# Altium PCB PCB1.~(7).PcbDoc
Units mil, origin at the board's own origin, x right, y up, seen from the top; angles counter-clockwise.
Board outline 2228.35 x 2228.35 mil, 2 copper layers (Top Layer, Bottom Layer); 14 components, 9 nets, 44 pads, 0 vias.
Unrouted connection lines stored in the file: 2.
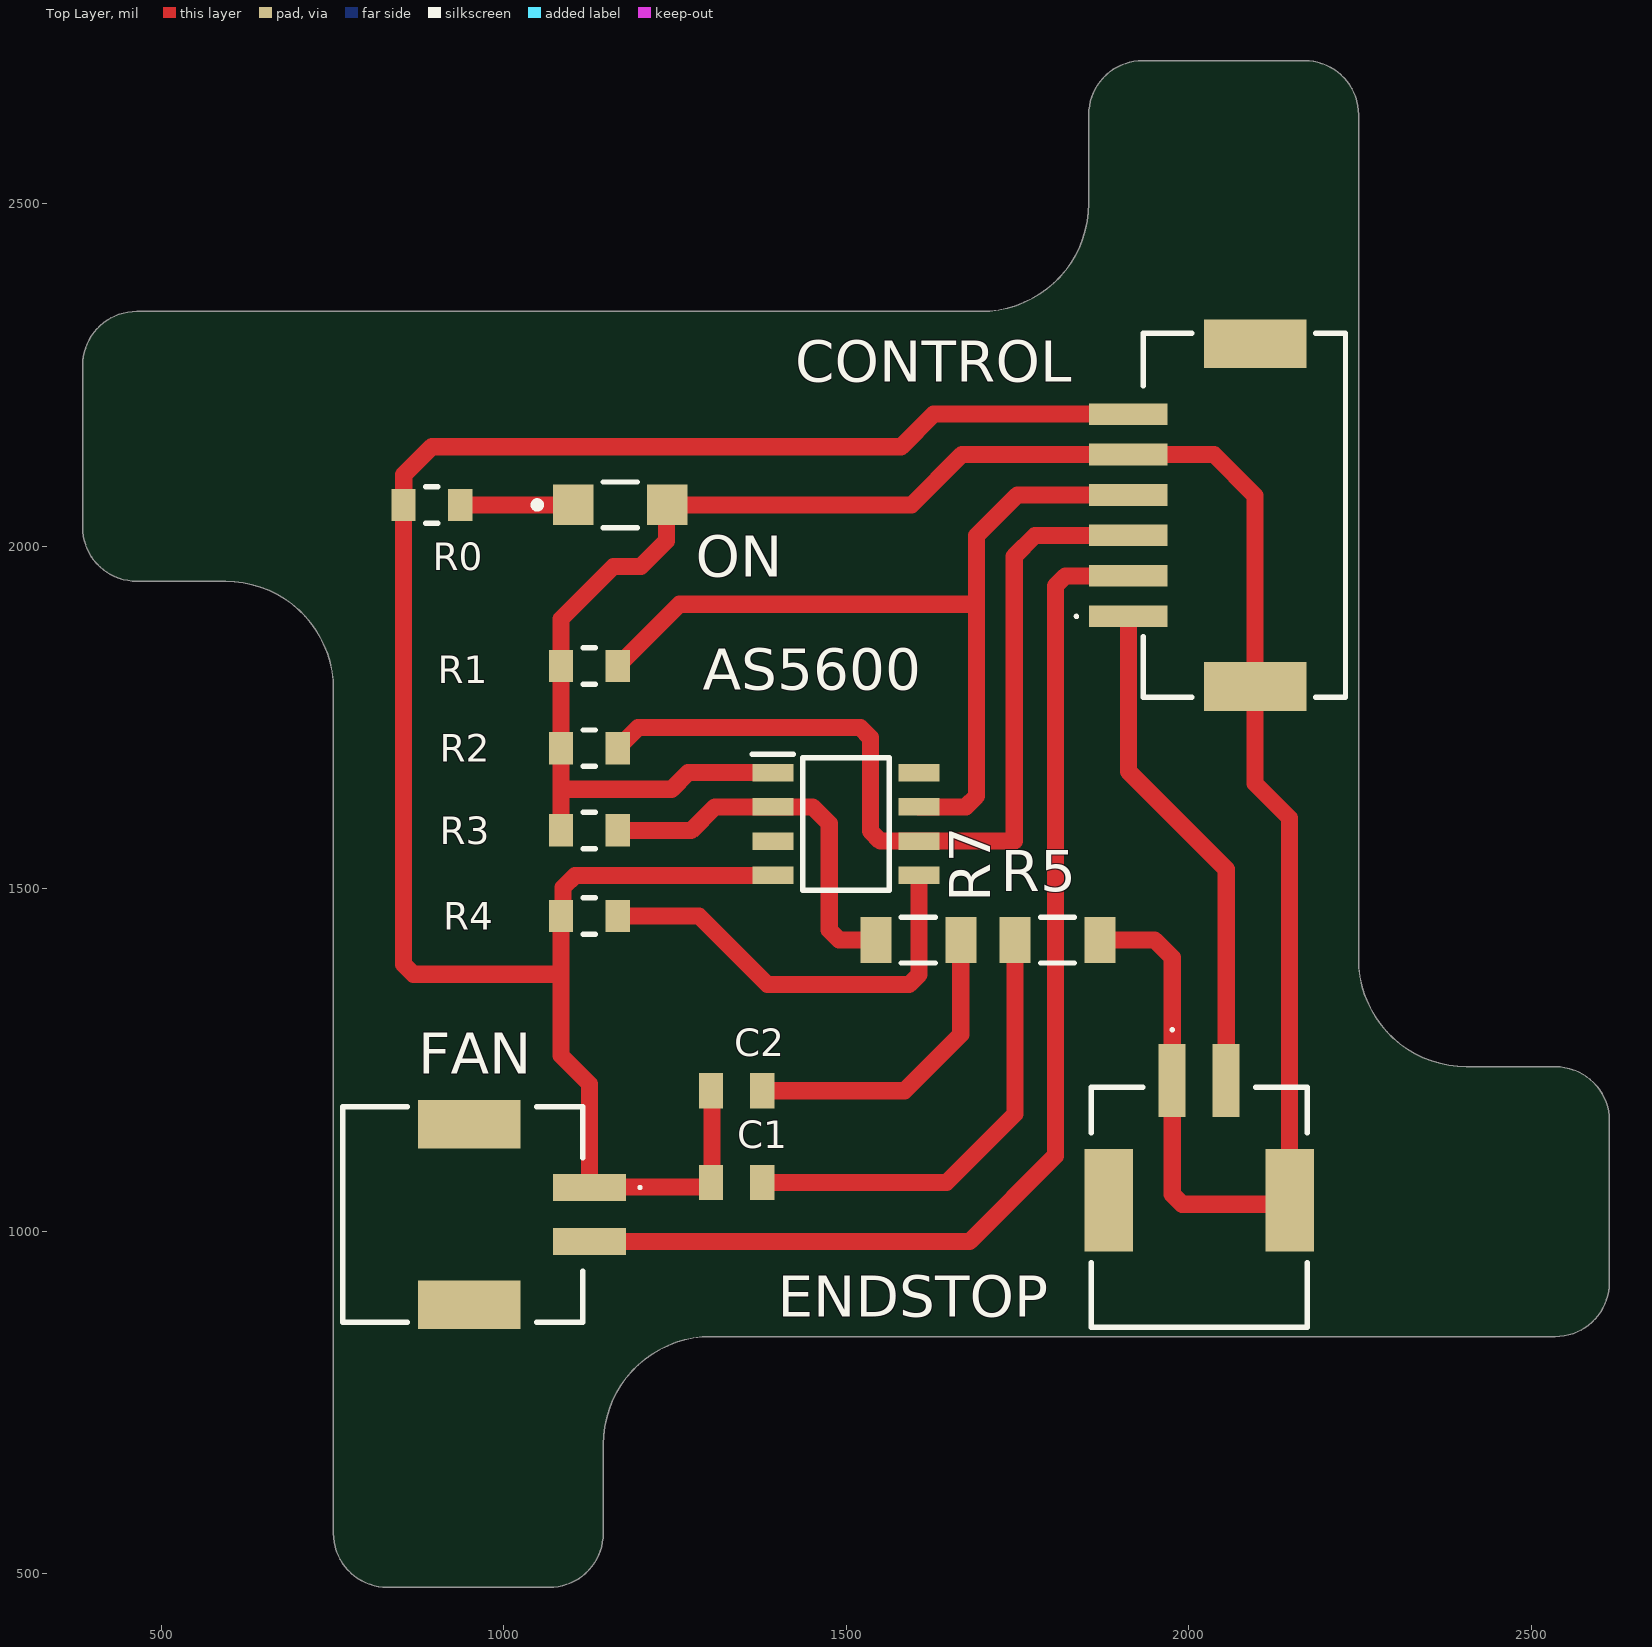
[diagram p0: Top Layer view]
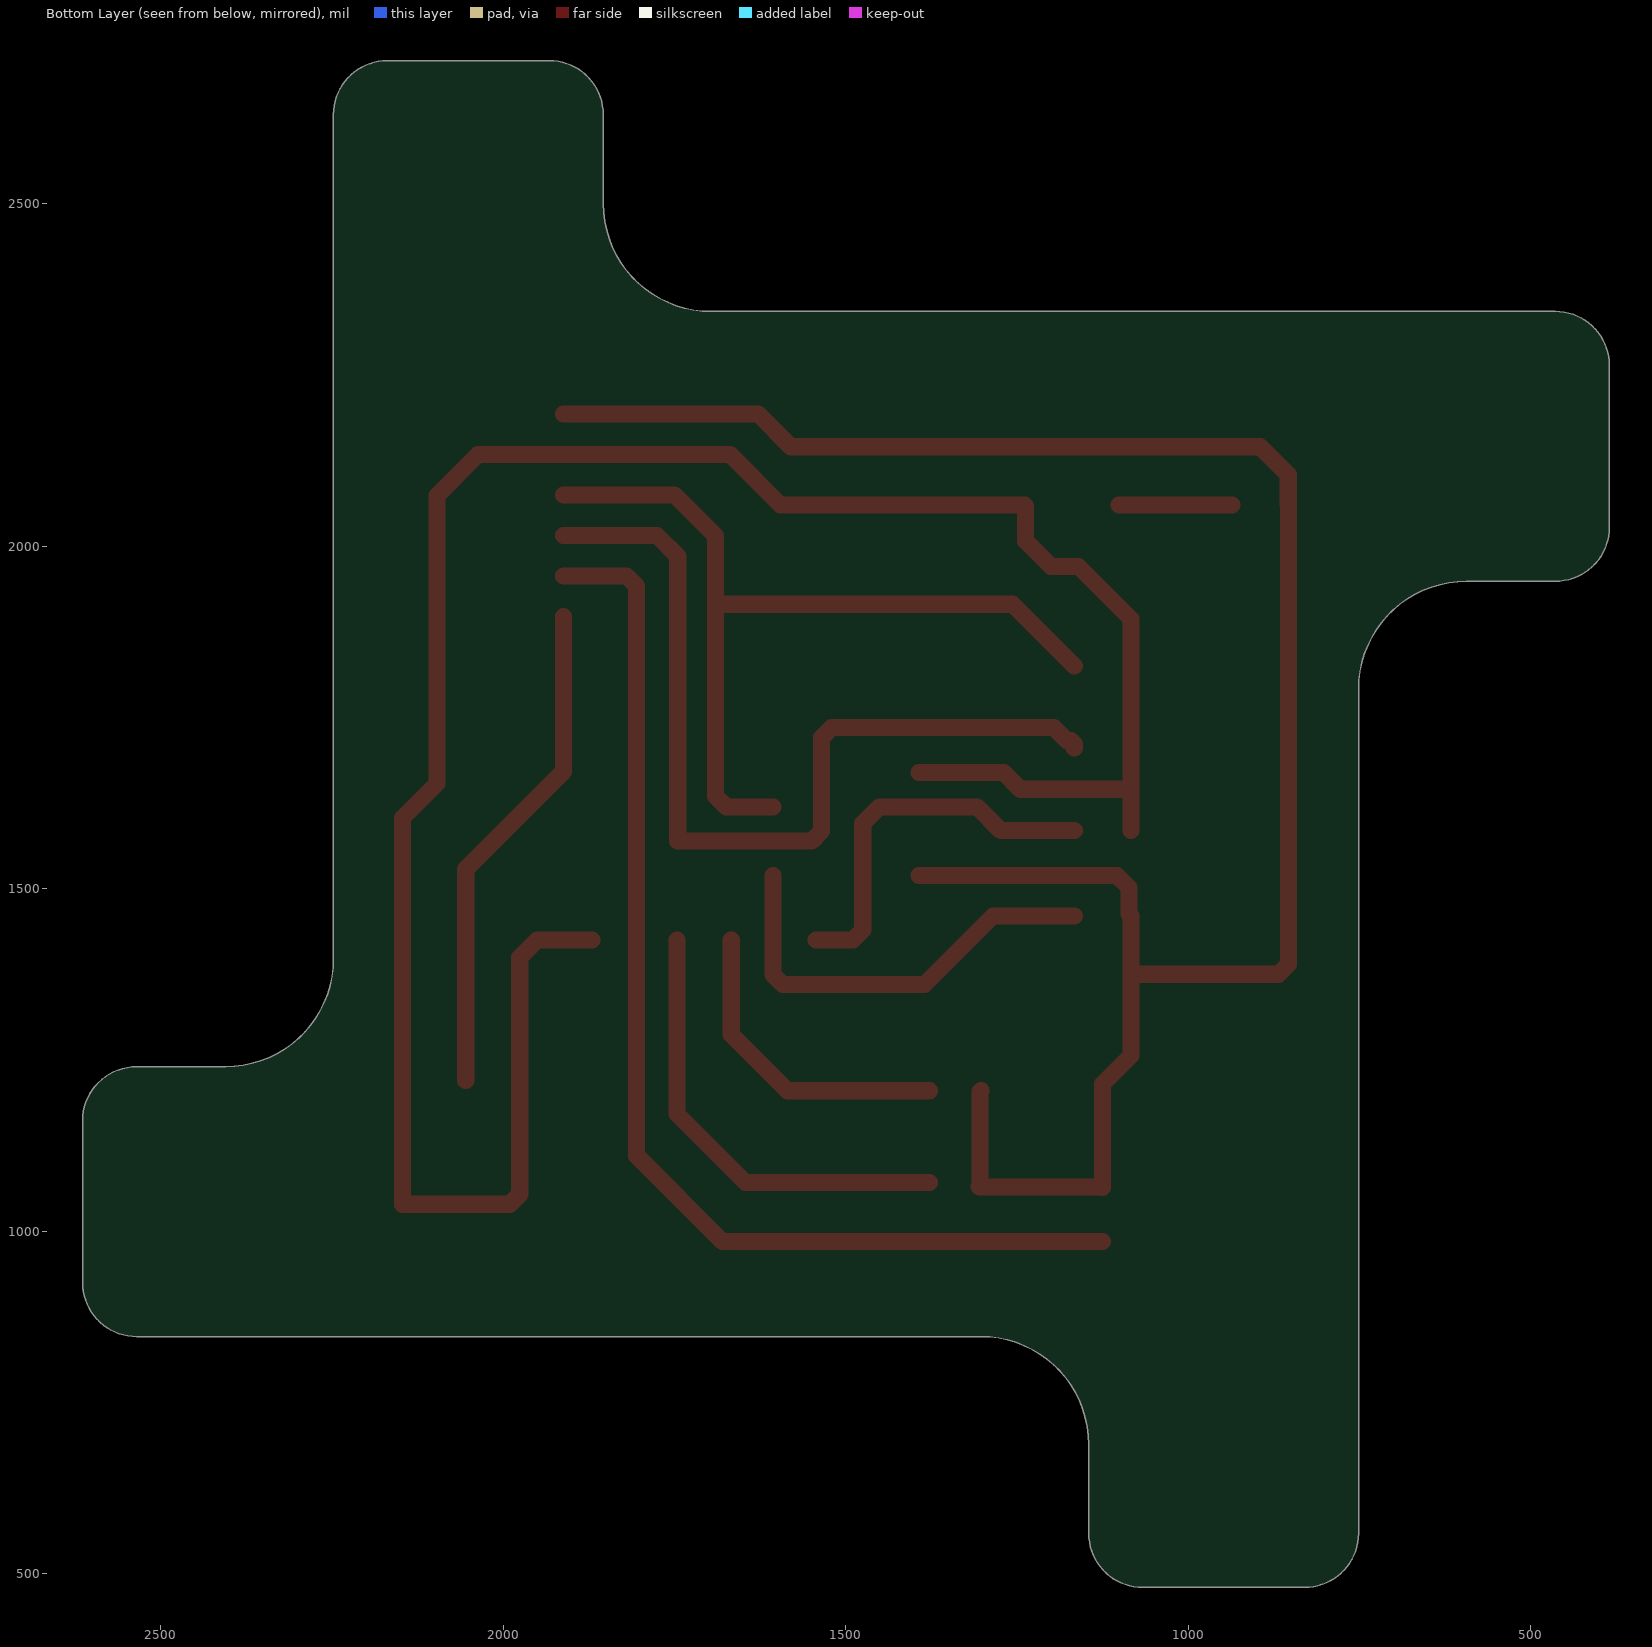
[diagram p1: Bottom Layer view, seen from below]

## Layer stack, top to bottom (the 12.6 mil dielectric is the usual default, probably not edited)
Top Solder: solder mask 0.4, Solder Resist, Dk 3.5
Top Layer: signal copper 1.4
Dielectric 1: dielectric 12.6, FR-4, Dk 4.8
Bottom Layer: signal copper 1.4
Bottom Solder: solder mask 0.4, Solder Resist, Dk 3.5

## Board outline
751.46,558.9 ccw(c830.2,558.9) 830.2,480.16 1066.42,480.16 ccw(c1066.42,558.9) 1145.16,558.9 1145.16,688.82 cw(c1302.64,688.82) 1302.64,846.3 2534.92,846.3 ccw(c2534.92,925.04) 2613.66,925.04 2613.66,1161.26 ccw(c2534.92,1161.26) 2534.92,1240 2405,1240 cw(c2405,1397.48) 2247.52,1397.48 2247.52,2629.76 ccw(c2168.78,2629.76) 2168.78,2708.5 1932.56,2708.5 ccw(c1932.56,2629.76) 1853.82,2629.76 1853.82,2499.84 cw(c1696.34,2499.84) 1696.34,2342.36 464.06,2342.36 ccw(c464.06,2263.62) 385.31,2263.62 385.31,2027.4 ccw(c464.06,2027.4) 464.06,1948.66 593.98,1948.66 cw(c593.98,1791.18) 751.46,1791.18

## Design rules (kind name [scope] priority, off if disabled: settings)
Clearance [All] p1: gap=10 ignorepadtopadclearanceinfootprint=FALSE
PolygonConnect [All] p1: connectstyle=Relief reliefconductorwidth=10 reliefentries=4 polygonreliefangle="90 Angle" airgapwidth=10
RoutingVias [All] p1: holewidth=28 width=50 viastyle="Through Hole" minholewidth=28 minwidth=50 maxholewidth=28 maxwidth=50
SolderMaskExpansion [All] p1: expansion=4 istentingtop=FALSE
SupplyNets "Schematic Supply Nets_2" [InNet('+5')] p1: voltage=0.000
SupplyNets "Schematic Supply Nets_1" [InNet('+3.3')] p2: voltage=0.000
SupplyNets "Schematic Supply Nets" [InNet('GND')] p3: voltage=0.000
Width [All] p1: maxlimit=25 minlimit=25 preferedwidth=25
30 further rules are at their usual default settings.

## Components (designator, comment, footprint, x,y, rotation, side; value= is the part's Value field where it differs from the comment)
AS5600 "AS5600-ASOM" SOIC127P600X175-8N 1499.49,1594.33 r0 top (schematic designator IC1)
C1 "885012007085" WCAP-CSGP_0805_L2W1.25H0.6_Reflow 1340,1071.21 r0 top
C2 "885012007085" WCAP-CSGP_0805_L2W1.25H0.6_Reflow 1340,1205 r0 top
CONTROL "C" SM06BZESSTBLFSN 2070,2045 r270 top
ENDSTOP "SM02B-PASS-TBT__LF__SN_" SM02BPASSTBTLFSN 2015,1040 r180 top
FAN "SM02B-PASS-TBT__LF__SN_" SM02BPASSTBTLFSN 944.88,1024.37 r90 top (schematic designator VM_GND_?)
ON "LTST-C150AKT" FP-LTST-C150AKT-MFG 1170,2060 r0 top
R0 "AC0805JR-0710RL" FP-AC0805-MFG 895,2060 r180 top value=10Ω
R1 "AC0805JR-0710RL" FP-AC0805-MFG 1125,1825 r180 top value=10Ω
R2 "AC0805JR-0710RL" FP-AC0805-MFG 1125,1705 r180 top value=10Ω
R3 "AC0805JR-0710RL" FP-AC0805-MFG 1125,1585 r0 top value=10Ω
R4 "AC0805JR-0710RL" FP-AC0805-MFG 1125,1460 r0 top value=10Ω
R5 "CSR1206FT33L0" FP-CSR1206-MFG 1807.99,1425 r180 top
R7 "CSR1206FT33L0" FP-CSR1206-MFG 1605,1425 r180 top

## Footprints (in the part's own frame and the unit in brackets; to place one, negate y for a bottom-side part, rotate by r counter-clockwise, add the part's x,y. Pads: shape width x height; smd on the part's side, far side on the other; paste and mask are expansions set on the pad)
FP-AC0805-MFG [mm]
  rect 0.9x1.2 smd paste+0 mask+0: 1(-1.05,0) 2(1.05,0)
  silkscreen extent -0.23,-0.67 0.23,0.67, body extent -1.6,-0.77 1.6,0.77, height 0.25
FP-CSR1206-MFG [mm]
  rect 1.15x1.7 smd paste+0 mask+0: 1(-1.575,0) 2(1.575,0)
  silkscreen extent -0.63,-0.85 0.63,0.85, body extent -2.25,-0.95 2.25,0.95, height 0.25
FP-LTST-C150AKT-MFG [mm]
  rect 1.5x1.5 smd paste+0 mask+0: 1(-1.75,0) 2(1.75,0)
  silkscreen extent -3.2,-0.85 0.63,0.85, body extent -2.6,-0.95 2.6,0.95, height 0.25
SM02BPASSTBTLFSN [mm]
  rect 1x2.7 smd: 1(1,-4.575) 2(-1,-4.575)
  rect 1.8x3.8 smd: 3(3.35,-0.125) 4(-3.35,-0.125)
  silkscreen extent -4,-6.5 4,4.57, body extent -4.07,-5.82 4.07,4.57, height 5.8
SM06BZESSTBLFSN [mm]
  rect 0.8x2.9 smd: 1(3.75,-4.025) 2(2.25,-4.025) 3(0.75,-4.025) 4(-0.75,-4.025) 5(-2.25,-4.025) 6(-3.75,-4.025)
  rect 1.8x3.8 smd: 7(6.35,0.675) 8(-6.35,0.675)
  silkscreen extent -6.75,-6 6.75,4.03, body extent -7.07,-5.4 7.07,4.03, height 5.9
SOIC127P600X175-8N [mm]
  rect 1.525x0.65 smd: 1(-2.712,1.905) 2(-2.712,0.635) 3(-2.712,-0.635) 4(-2.712,-1.905) 5(2.712,-1.905) 6(2.712,-0.635) 7(2.712,0.635) 8(2.712,1.905)
  silkscreen extent -3.47,-2.45 1.6,2.58, body extent -3,-2.45 3,2.45, height 1.75
WCAP-CSGP_0805_L2W1.25H0.6_Reflow [mm] "Ceramic Capacitors, body 2x1.25mm"
  rect 0.9x1.3 smd: 1(-0.95,0) 2(0.95,0)
  body extent -1,-0.63 1,0.63, height 0.6

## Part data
AS5600: "Integrated Circuit", Manufacturer_Name="ams OSRAM", Mouser Part Number=985-AS5600-ASOM
C1 C2: library part CMP-03913-89205616-2, "Cap, Mlcc, 330PF, 100V, C0G/NP0, 0805;", Capacitance=330pF, Insulation Resistance=10GΩ, Max Operating Temperature=125°C, Min Operating Temperature=-55°C, Voltage Rating=100V
CONTROL: library part SM06B-ZESS-TB_LF__SN_, "Connector", Manufacturer_Name="JST (JAPAN SOLDERLESS TERMINALS)", Manufacturer_Part_Number=SM06B-ZESS-TB(LF)(SN)
ENDSTOP FAN: "Connector", Arrow Part Number="SM02B-PASS-TBT (LF)(SN)", Manufacturer_Name="JST (JAPAN SOLDERLESS TERMINALS)"
ON: library part CMP-22017-000004-1, "LED AMBER CLEAR SMD", Colour=Amber, Forward Current=30mA, Forward Voltage=2.1V, Manufacturer=Lite-On, Package=0, Power Dissipation=100mW, Reverse Voltage=5V, Temperature="-55°C to +85°C", Temperature Range High=+85°C, Temperature Range Low=-55°C
R0 R1 R2 R3 R4: library part CMP-03412-037687-1, "RES SMD 10 OHM 5% 1/8W 0805", Manufacturer=Yageo, Package=AC0805, Power Rating=1/8W, Resistance=10Ω, Temperature="-55°C to +155°C", Temperature Range High=+155°C, Temperature Range Low=-55°C, Tolerance=0.05, Voltage Rating=150V
R5 R7: library part CMP-26527-002831-1, "General Purpose Thick Film Chip Resistor, 1206, 33mΩ, 1%, 0.5W", Case/Package=1206, Max Operating Temperature=155°C, Max Power Dissipation=500mW, Min Operating Temperature=-55°C, Package Quantity=5000, Resistance=33mR, Resistor Type="Thick Film", Temperature Coefficient=100ppm/°C, Tolerance=1%

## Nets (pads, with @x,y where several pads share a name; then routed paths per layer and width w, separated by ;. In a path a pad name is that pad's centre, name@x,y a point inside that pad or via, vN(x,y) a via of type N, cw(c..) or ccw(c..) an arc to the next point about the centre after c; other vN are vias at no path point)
+3.3: AS5600.2 C2.2 R3.2 R7.1 R7.2 | length 1024.2
  Top Layer w25: R3.2 1273.19,1585 1273.52,1584.67 1308.19,1619.33 1450.67,1619.33 1475,1595 1475,1439.64 1489.64,1425 R7.2 ; C2.2 1585,1205 1667.01,1287.01 R7.1
+5: AS5600.1 C1.2 CONTROL.5 CONTROL.7 ENDSTOP.1 ENDSTOP.4 ON.2 R1.2 R2.2 R3.1 R5.1 R5.2 | length 4148.7
  Top Layer w25: R3.1 1083.66,1641.34 ; C1.2 1646.21,1071.21 1745.98,1170.98 R5.2 ; AS5600.1 1269.33,1669.33 1245,1645 1087.32,1645 1083.66,1641.34 ; R5.1 1950,1425 1975.63,1399.37 ENDSTOP.1 1975.63,1054.01 1990.27,1039.37 ENDSTOP.4@2146.89,1039.37 ; ENDSTOP.4 2146.89,1603.11 2096.57,1653.43 CONTROL.7 2096.57,2073.43 2036.42,2133.58 CONTROL.5 1668.58,2133.58 1595,2060 ON.2 1237.62,2058.72 1237.62,2007.62 1200,1970 1160,1970 1083.66,1893.66 R1.2 R2.2 1083.66,1641.34
GND: AS5600.4 C1.1 C2.1 CONTROL.6 FAN.1 R0.2 R4.1 | length 3136.3
  Top Layer w25: C2.1 1303.9,1203.7 1303.9,1066.3 1305.2,1065 1304.57,1064.37 1125.63,1064.37 FAN.1 1125,1215 1083.66,1256.34 1083.66,1375 ; AS5600.4 1104.33,1519.33 1086.52,1501.52 1086.52,1462.86 R4.1 1083.66,1375 ; CONTROL.6 1627.64,2192.64 1580,2145 895,2145 854.02,2104.02 854.02,2060.36 R0.2 853.66,1389.64 868.31,1375 1083.66,1375
NetAS5600_5: AS5600.5 R4.2 | length 632.1
  Top Layer w25: R4.2 1285,1460 1385,1360 1591.62,1360 1606.26,1374.64 AS5600.5
NetCONTROL_1: CONTROL.1 ENDSTOP.2 | length 736.4
  Top Layer w25: CONTROL.1 1911.54,1671.15 2054.37,1528.32 ENDSTOP.2
NetCONTROL_2: CONTROL.2 FAN.2 | length 1676.2
  Top Layer w25: FAN.2 1680,985 1805,1110 1805,1941.77 1819.64,1956.42 CONTROL.2
NetON_1: ON.1 R0.1 | length 164.8
  Top Layer w25: R0.1 ON.1
SCL: AS5600.7 CONTROL.4 R1.1 | length 1277.4
  Top Layer w25: R1.1 1256.34,1915 1690,1915 ; AS5600.7 1674.33,1619.33 1690,1635 1690,1915 ; CONTROL.4 1749.53,2074.53 1690,2015 1690,1915
SDA: AS5600.6 CONTROL.3 R2.1 | length 1337.9
  Top Layer w25: R2.1 1166.34,1710.91 1171.56,1716.12 1177.46,1716.12 1196.34,1735 1520.36,1735 1535,1720.36 1535,1583.98 1549.64,1569.33 1745,1569.33 1745,1985 1775.47,2015.47 CONTROL.3
pads on no net: AS5600.3 AS5600.8 CONTROL.8 ENDSTOP.3 FAN.3 FAN.4

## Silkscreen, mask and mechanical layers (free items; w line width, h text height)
Mechanical 1:
  circle w1: c2495.55,952.6 r62.99
  circle w0.5: c503.43,2236.06 r62.99
  circle w0.5: c857.76,598.27 r62.99
  circle w0.5: c2141.22,2590.39 r62.99
  lines w0.5: 385.31,2027.4 ccw(c464.06,2027.4) 464.06,1948.66 593.98,1948.66 cw(c593.98,1791.18) 751.46,1791.18 751.46,558.9 ccw(c830.2,558.9) 830.2,480.16 1066.42,480.16 ccw(c1066.42,558.9) 1145.16,558.9 1145.16,688.82 cw(c1302.64,688.82) 1302.64,846.3 2534.92,846.3 ccw(c2534.92,925.04) 2613.66,925.04 2613.66,1161.26 ccw(c2534.92,1161.26) 2534.92,1240 2405,1240 cw(c2405,1397.48) 2247.52,1397.48 2247.52,2629.76 ccw(c2168.78,2629.76) 2168.78,2708.5 1932.56,2708.5 ccw(c1932.56,2629.76) 1853.82,2629.76 1853.82,2499.84 cw(c1696.34,2499.84) 1696.34,2342.36 464.06,2342.36 ccw(c464.06,2263.62) 385.31,2263.62 385.31,2027.4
